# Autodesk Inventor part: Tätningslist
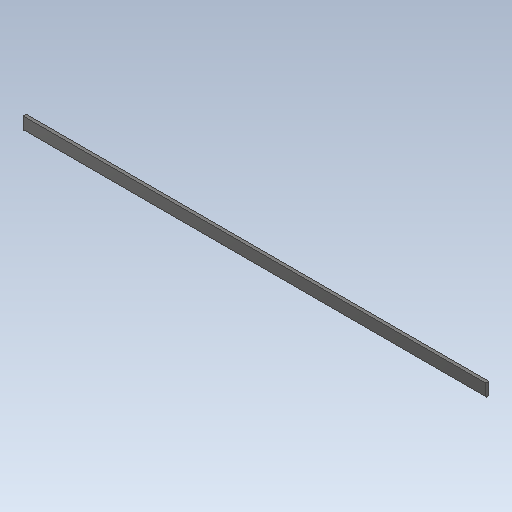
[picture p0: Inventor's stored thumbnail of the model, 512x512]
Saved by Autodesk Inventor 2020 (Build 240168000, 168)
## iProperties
Created: 2019-06
Part Number: Tätningslist
Material: Acetal Resin, Black
Document SubType Name: Modeling
Designer: cl
Density: 1.425 g/cm^3
Appearance: Smooth - Black
Author: cl
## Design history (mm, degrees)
sketch "Sketch1"
  geometry: L1 (4.9, 0)-(60, 0); L2 (60, 0)-(60, -14.8); L3 (60, -14.8)-(4.9, -14.8); L4 (0, -9.9)-(0, -4.9); A1 r 4.9 centre (4.9, -9.9) between (0, -9.9) and (4.9, -14.8); A2 r 4.9 centre (4.9, -4.9) between (4.9, 0) and (0, -4.9); 2 further points
  constraints: 8 end point, 4 point on circle, 4 point on line, 4 tangent, 2 centre point, 2 parallel, 1 equal radius, 1 horizontal, 1 perpendicular
  dimensions: "d0" = 60 distance of L2.end point (0, -14.8); "d1" = 14.8 distance of L1.end L2.end; "d2" = 4.9 radius of A1
extrude "Extrusion1" new body sketch "Sketch1" distance "d3" = 2192 (computed from Dagbredd); taper "d4" = 0 deg
body "Solid1"
other parameters: "Daghöjd" = 3254, "Dagbredd" = 2222
